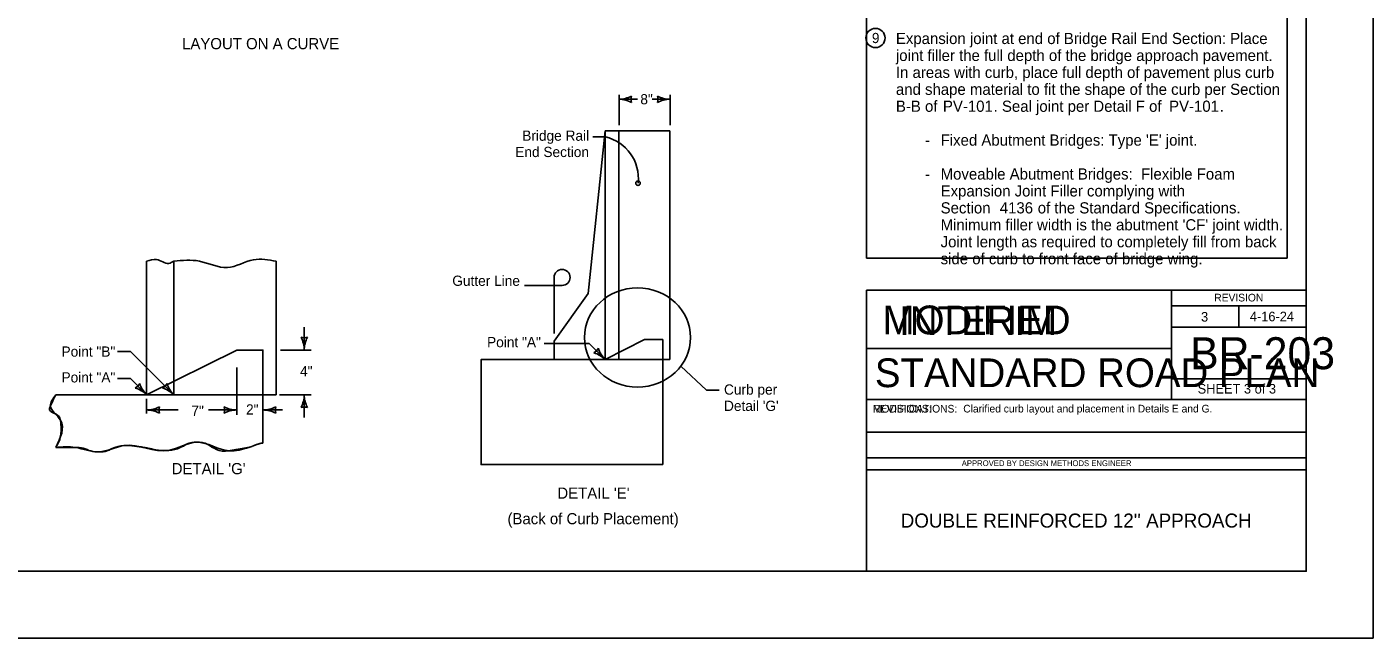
# Model space of a CAD drawing. Extents: x -2135039 to -2124495, y -2139046 to -2132546.
# Drawn here: x -2126601 to -2124495, y -2135130 to -2134174 of the extents above; entities that cross this region are included whole.
import ezdxf

# ---------------------------------------------------------------- set-up
doc = ezdxf.new("R2010")
doc.units = 0
for name, color, linetype in [('Barrier', 7, 'Continuous'), ('BridgeSuperStructureExisting', 7, 'Continuous'), ('Dimension', 7, 'Continuous'), ('dsnAlignmentCurveData', 7, 'Continuous'), ('dsnAlignmentStation', 7, 'Continuous'), ('dsnAlignmentTic', 7, 'Continuous'), ('dsnCellElements', 7, 'Continuous'), ('DsnShtPlotIdentification', 7, 'Continuous'), ('dsnStdLabel', 7, 'Continuous'), ('dsnStdLineWork', 7, 'Continuous'), ('PhoEdgeShoulderPaved', 7, 'Continuous'), ('TC_Barrier', 7, 'Continuous')]:
    doc.layers.add(name, color=color, linetype=linetype)

msp = doc.modelspace()

# ---------------------------------------------------------------- linework, layer by layer
at = {"layer": 'BridgeSuperStructureExisting'}
for p, q in [((-2125674.7, -2134328), (-2125674.7, -2134280.7)), ((-2125594.7, -2134328), (-2125594.7, -2134280.7)), ((-2125675, -2134287.4), (-2125645.9, -2134287.4)), ((-2125623, -2134287.4), (-2125594.7, -2134287.4)), ((-2125723, -2134591.1), (-2125696.3, -2134337.1)), ((-2125696, -2134346.3), (-2125715.5, -2134346.3)), ((-2125696.3, -2134337.1), (-2125595, -2134337.1)), ((-2125696.3, -2134337.1), (-2125696.3, -2134694.7)), ((-2125675, -2134337.1), (-2125675, -2134683.7)), ((-2125595, -2134337.1), (-2125595, -2134694.7)), ((-2126413.9, -2134540.8), (-2126413.9, -2134749.8)), ((-2126371.2, -2134540.8), (-2126371.2, -2134728.7)), ((-2126211.2, -2134540.8), (-2126211.2, -2134749.7)), ((-2125822.7, -2134578.7), (-2125783.8, -2134578.7)), ((-2125776.3, -2134654.1), (-2125776.3, -2134586.2)), ((-2125776.3, -2134665.8), (-2125723, -2134591.1)), ((-2125595, -2134631.5), (-2125595, -2134663.1)), ((-2126167.2, -2134644.1), (-2126167.2, -2134679.8)), ((-2126459.3, -2134682.2), (-2126438.8, -2134682.2)), ((-2126438.8, -2134682.2), (-2126371.2, -2134749.8)), ((-2126231.8, -2134679.8), (-2126272.5, -2134679.8)), ((-2126231.8, -2134825.3), (-2126231.8, -2134679.8)), ((-2126204.4, -2134679.8), (-2126156.5, -2134679.8)), ((-2125721.6, -2134669.4), (-2125791.9, -2134669.4)), ((-2125776.3, -2134694.7), (-2125776.3, -2134665.8)), ((-2125721.6, -2134669.4), (-2125696.3, -2134694.7)), ((-2125606, -2134663.1), (-2125635, -2134663.1)), ((-2125635, -2134663.1), (-2125606, -2134663.1)), ((-2125606, -2134858.9), (-2125606, -2134663.1)), ((-2125606, -2134663.1), (-2125606, -2134858.9)), ((-2125696.3, -2134694.7), (-2125606, -2134694.7)), ((-2125675, -2134683.7), (-2125675, -2134694.7)), ((-2125606, -2134694.7), (-2125595, -2134694.7)), ((-2126439.1, -2134724.6), (-2126459.3, -2134724.6)), ((-2126439.1, -2134724.6), (-2126413.9, -2134749.8)), ((-2126272.7, -2134707.2), (-2126272.7, -2134781.1)), ((-2125578, -2134705.1), (-2125538, -2134742.8)), ((-2126371.2, -2134728.7), (-2126371.2, -2134749.8)), ((-2125538, -2134742.8), (-2125518.2, -2134742.8)), ((-2126555.9, -2134749.8), (-2126413.9, -2134749.8)), ((-2126413.8, -2134749.8), (-2126415, -2134749.8)), ((-2126231.8, -2134749.8), (-2126413.9, -2134749.8)), ((-2126413.9, -2134756.1), (-2126413.9, -2134779.1)), ((-2126231.8, -2134749.8), (-2126211.2, -2134749.8)), ((-2126206, -2134749.7), (-2126156.5, -2134749.7)), ((-2126167.2, -2134749.7), (-2126167.2, -2134785.5)), ((-2126413.8, -2134773.6), (-2126364.4, -2134773.6)), ((-2126316.8, -2134773.6), (-2126272.7, -2134773.6)), ((-2126231.8, -2134773.6), (-2126201.3, -2134773.6))]:
    msp.add_line(p, q, dxfattribs=at)
for points in [[(-2126231.8, -2134825.3), (-2126231.8, -2134679.8), (-2126272.5, -2134679.8), (-2126413.9, -2134749.8), (-2126555.9, -2134749.8)], [(-2126413.9, -2134749.8), (-2126272.5, -2134679.8)], [(-2125696.3, -2134694.7), (-2125635, -2134663.1)], [(-2125696.3, -2134694.7), (-2125635, -2134663.1)], [(-2125606, -2134858.9), (-2125890.4, -2134858.9), (-2125890.4, -2134694.7), (-2125744.3, -2134694.7), (-2125696.3, -2134694.7)], [(-2125606, -2134858.9), (-2125890.4, -2134858.9), (-2125890.4, -2134694.7), (-2125744.3, -2134694.7), (-2125696.3, -2134694.7)]]:
    msp.add_lwpolyline(points, dxfattribs=at)
msp.add_circle((-2125273.5, -2134191.6), 15, dxfattribs=at)
msp.add_arc((-2125711.1, -2134411.2), 66.7, 353.5756, 76.8823, dxfattribs=at)
msp.add_ellipse((-2125645.7, -2134660.1), major_axis=(83, 0), ratio=0.93542, dxfattribs=at)
for points in [[(-2126413.9, -2134540.8), (-2126398.2, -2134538.3), (-2126379.1, -2134544.2), (-2126371.2, -2134540.8)], [(-2126371.2, -2134540.8), (-2126331.1, -2134540.8), (-2126287.4, -2134550.8), (-2126246.6, -2134538.6), (-2126211.2, -2134540.8)], [(-2126555.9, -2134749.8), (-2126564.2, -2134767.4), (-2126548.5, -2134789.6), (-2126555.7, -2134832.2)], [(-2126555.7, -2134832.2), (-2126525.2, -2134832.2), (-2126489, -2134839.2), (-2126449.3, -2134829.3), (-2126379.4, -2134836.9), (-2126335.6, -2134824.1), (-2126284.3, -2134837.5), (-2126253.8, -2134832.2)]]:
    msp.add_spline(points, degree=3, dxfattribs=at)
for points, degree in [([(-2126555.9, -2134749.8), (-2126558.7, -2134755.7), (-2126561.5, -2134761.5), (-2126564.2, -2134767.4), (-2126568.1, -2134775.6), (-2126549.5, -2134781.8), (-2126548.5, -2134789.6), (-2126547, -2134801.9), (-2126548.1, -2134819.7), (-2126555.7, -2134832.2)], 3), ([(-2126555.7, -2134832.2), (-2126545.5, -2134832.2), (-2126535.4, -2134832.2), (-2126525.2, -2134832.2), (-2126512.9, -2134832.2), (-2126501, -2134838.8), (-2126489, -2134839.2), (-2126475.7, -2134839.7), (-2126462.6, -2134830.1), (-2126449.3, -2134829.3)], 3), ([(-2126449.3, -2134829.3), (-2126442.2, -2134828.9), (-2126435, -2134829.6), (-2126427.7, -2134830.7)], 2), ([(-2126427.7, -2134830.7), (-2126411.5, -2134833.1), (-2126395, -2134837.6), (-2126379.4, -2134836.9)], 2), ([(-2126379.4, -2134836.9), (-2126364.6, -2134836.2), (-2126350.3, -2134824.4), (-2126335.6, -2134824.1), (-2126318.5, -2134823.6), (-2126301.7, -2134840.5), (-2126284.3, -2134837.5)], 3), ([(-2126253.8, -2134832.2), (-2126252.9, -2134832), (-2126251.9, -2134831.7), (-2126251, -2134831.3), (-2126250.1, -2134831), (-2126249.2, -2134830.7), (-2126248.3, -2134830.3), (-2126246.4, -2134829.6), (-2126244.6, -2134828.9), (-2126242.8, -2134828.2), (-2126241, -2134827.5), (-2126239.1, -2134826.9), (-2126237.3, -2134826.3), (-2126236.4, -2134826), (-2126235.5, -2134825.8), (-2126234.5, -2134825.6), (-2126234.1, -2134825.6), (-2126233.6, -2134825.5), (-2126233.2, -2134825.4), (-2126232.7, -2134825.4), (-2126232.3, -2134825.3), (-2126231.8, -2134825.3)], 3), ([(-2126253.8, -2134832.2), (-2126252.9, -2134832), (-2126251.9, -2134831.7), (-2126251, -2134831.3), (-2126250.1, -2134831), (-2126249.2, -2134830.7), (-2126248.3, -2134830.3), (-2126246.4, -2134829.6), (-2126244.6, -2134828.9), (-2126242.8, -2134828.2), (-2126241, -2134827.5), (-2126239.1, -2134826.9), (-2126237.3, -2134826.3), (-2126236.4, -2134826), (-2126235.5, -2134825.8), (-2126234.5, -2134825.6), (-2126234.1, -2134825.6), (-2126233.6, -2134825.5), (-2126233.2, -2134825.4), (-2126232.7, -2134825.4), (-2126232.3, -2134825.3), (-2126231.8, -2134825.3)], 3), ([(-2126284.3, -2134837.5), (-2126278.3, -2134836.4), (-2126272.3, -2134835.4), (-2126266.3, -2134834.4)], 2), ([(-2126266.3, -2134834.4), (-2126262.2, -2134833.7), (-2126258, -2134832.9), (-2126253.8, -2134832.2)], 2)]:
    msp.add_open_spline(points, degree=degree, dxfattribs=at)
at = {"layer": 'Dimension'}
for p, q in [((-2124810.4, -2134585.9), (-2124810.4, -2134677.3)), ((-2124810.4, -2134610.9), (-2124599.4, -2134610.9)), ((-2124704.9, -2134610.9), (-2124704.9, -2134644.1)), ((-2124810.4, -2134644.1), (-2124599.4, -2134644.1)), ((-2125287.5, -2134677.3), (-2124810.4, -2134677.3)), ((-2124810.4, -2134677.3), (-2124810.4, -2134757.3)), ((-2124599.4, -2134725.1), (-2124810.4, -2134725.1)), ((-2125287.5, -2134757.3), (-2124599.4, -2134757.3)), ((-2125287.5, -2134808.3), (-2124599.4, -2134808.3)), ((-2125287.5, -2134848.3), (-2124599.4, -2134848.3)), ((-2125287.5, -2134867.3), (-2124599.4, -2134867.3))]:
    msp.add_line(p, q, dxfattribs=at)
msp.add_lwpolyline([(-2125287.5, -2134585.9), (-2124599.4, -2134585.9), (-2124599.4, -2135026), (-2125287.5, -2135026)], close=True, dxfattribs=at)
msp.add_lwpolyline([(-2125287.5, -2134585.9), (-2124599.4, -2134585.9), (-2124599.4, -2135026), (-2125287.5, -2135026)], close=True, dxfattribs=at)
at = {"layer": 'dsnAlignmentStation'}
msp.add_lwpolyline([(-2127734.4, -2133016), (-2124599.4, -2133016), (-2124599.4, -2135026), (-2127734.4, -2135026)], close=True, dxfattribs=at)
at = {"layer": 'dsnCellElements'}
for centre, radius, start, end in [((-2125675, -2134244.9), 42.5, 270, 298.0725), ((-2125639.3, -2134287.4), 16.4, 162.2666, 197.7334), ((-2125630.3, -2134287.4), 16.4, 342.2666, 17.7333), ((-2125594.7, -2134244.9), 42.5, 241.9275, 270), ((-2125675, -2134329.9), 42.5, 61.9275, 90), ((-2125594.7, -2134329.9), 42.5, 90, 118.0725), ((-2126167.2, -2134644.2), 16.4, 252.2666, 287.7333), ((-2126209.7, -2134679.8), 42.5, 360, 28.0725), ((-2126124.7, -2134679.8), 42.5, 151.9275, 180), ((-2125721.5, -2134669.5), 16.4, 297.2666, 332.7333), ((-2125666.2, -2134664.7), 42.5, 196.9275, 225), ((-2125726.3, -2134724.8), 42.5, 45, 73.0725), ((-2126439.1, -2134724.6), 16.4, 297.2666, 332.7333), ((-2126443.9, -2134779.9), 42.5, 45, 73.0725), ((-2126383.8, -2134719.8), 42.5, 196.9275, 225), ((-2126396.4, -2134724.6), 16.4, 297.2666, 332.7333), ((-2126401.3, -2134779.9), 42.5, 45, 73.0725), ((-2126341.2, -2134719.8), 42.5, 196.9275, 225), ((-2126209.7, -2134749.7), 42.5, 331.9275, 360), ((-2126124.7, -2134749.7), 42.5, 180, 208.0725), ((-2126413.8, -2134731.1), 42.5, 270, 298.0725), ((-2126413.8, -2134816.1), 42.5, 61.9275, 90), ((-2126378.1, -2134773.6), 16.4, 162.2666, 197.7334), ((-2126308.3, -2134773.6), 16.4, 342.2666, 17.7333), ((-2126272.7, -2134731.1), 42.5, 241.9275, 270), ((-2126272.7, -2134816.1), 42.5, 90, 118.0725), ((-2126231.8, -2134731.1), 42.5, 270, 298.0725), ((-2126231.8, -2134816.1), 42.5, 61.9275, 90), ((-2126196.1, -2134773.6), 16.4, 162.2666, 197.7334), ((-2126167.2, -2134785.4), 16.4, 72.2666, 107.7334)]:
    msp.add_arc(centre, radius, start, end, dxfattribs=at)
at = {"layer": 'dsnStdLineWork'}
msp.add_lwpolyline([(-2127838.9, -2135130.5), (-2124494.9, -2135130.5), (-2124494.9, -2132546.5), (-2127838.9, -2132546.5)], close=True, dxfattribs=at)
at = {"layer": 'PhoEdgeShoulderPaved'}
for p, q in [((-2125287.5, -2133066), (-2125287.5, -2134535.9)), ((-2124629.4, -2133066), (-2124629.4, -2134535.9)), ((-2124629.4, -2134535.9), (-2125287.5, -2134535.9))]:
    msp.add_line(p, q, dxfattribs=at)
at = {"layer": 'TC_Barrier'}
for p, q in [((-2125776.3, -2134586.2), (-2125776.3, -2134566.2)), ((-2125763.8, -2134578.7), (-2125783.8, -2134578.7))]:
    msp.add_line(p, q, dxfattribs=at)
msp.add_circle((-2125644.9, -2134418.7), 3.54, dxfattribs=at)
msp.add_arc((-2125763.8, -2134566.2), 12.5, 270, 180, dxfattribs=at)

# ---------------------------------------------------------------- texts
at = {"layer": 'Barrier'}
for s, height, p in [('9', 16, (-2125279.1, -2134199.6)), ('Expansion joint at end of Bridge Rail End Section: Place', 17.5, (-2125241.5, -2134201.1)), ('joint filler the full depth of the bridge approach pavement.', 17.5, (-2125241.5, -2134227.6)), ('In areas with curb, place full depth of pavement plus curb', 17.5, (-2125241.5, -2134254.1)), ('and shape material to fit the shape of the curb per Section', 17.5, (-2125241.5, -2134280.6)), ('B-B of ', 17.5, (-2125241.5, -2134307.1)), ('PV-101', 17.5, (-2125167.9, -2134307.1)), ('PV-101', 17.5, (-2125167.9, -2134307.1)), ('. Seal joint per Detail F of ', 17.5, (-2125088.6, -2134307.1)), ('PV-101', 17.5, (-2124814.1, -2134307.1)), ('PV-101', 17.5, (-2124814.1, -2134307.1)), ('.', 17.5, (-2124734.8, -2134307.1)), ("Fixed Abutment Bridges: Type 'E' joint.", 17.5, (-2125171.5, -2134360.1)), ('       -', 17.5, (-2125241.5, -2134360.1)), ('       -', 17.5, (-2125241.5, -2134413.1)), ('Moveable Abutment Bridges:  Flexible Foam', 17.5, (-2125171.5, -2134413.1)), ('Expansion Joint Filler complying with ', 17.5, (-2125171.5, -2134439.6)), ('Section ', 17.5, (-2125171.5, -2134466.1)), ('4136', 17.5, (-2125079, -2134466.1)), ('4136', 17.5, (-2125079, -2134466.1)), (' of the Standard Specifications.', 17.5, (-2125026.1, -2134466.1)), ("Minimum filler width is the abutment 'CF' joint width.", 17.5, (-2125171.5, -2134492.6)), ('Joint length as required to completely fill from back ', 17.5, (-2125171.5, -2134519.1)), ('side of curb to front face of bridge wing.', 17.5, (-2125171.5, -2134545.6))]:
    msp.add_text(s, height=height, dxfattribs=at).set_placement(p)
at = {"layer": 'BridgeSuperStructureExisting'}
for s, height, p in [('LAYOUT ON A CURVE', 17.5, (-2126358.3, -2134209.2)), ('8"', 16, (-2125641.3, -2134295.4)), ('Bridge Rail ', 16, (-2125826.1, -2134352.4)), ('End Section', 16, (-2125837, -2134377.9)), ('Gutter Line', 16, (-2125935.5, -2134579.4)), ('Point "A"', 16, (-2125881.1, -2134675.4)), ('Point "B"', 16, (-2126546.9, -2134690.2)), ('Point "A"', 16, (-2126546.9, -2134730.5)), ('4"', 16, (-2126173.7, -2134720.9)), ('Curb per', 16, (-2125510.4, -2134749.6)), ('7"', 16, (-2126343.7, -2134782.8)), ('2"', 16, (-2126258.2, -2134780.7)), ("Detail 'G'", 16, (-2125510.4, -2134775.1)), ("DETAIL 'G'", 17.5, (-2126374.5, -2134874.1)), ("DETAIL 'E'", 17.5, (-2125771.1, -2134912.4))]:
    msp.add_text(s, height=height, dxfattribs=at).set_placement(p)
at = {"layer": 'Dimension'}
for s, height, p in [('REVISION', 12, (-2124743.4, -2134603.8)), ('3', 15, (-2124764.1, -2134635.3)), ('4-16-24', 15, (-2124687.8, -2134634.8)), ('BR-203', 50, (-2124781.2, -2134709.8)), ('STANDARD ROAD PLAN', 45.001, (-2125274.4, -2134737.9)), ('SHEET 3 of 3', 15, (-2124769.4, -2134747.9)), ('Clarified curb layout and placement in Details E and G.', 12, (-2125136.1, -2134777.5)), ('APPROVED BY DESIGN METHODS ENGINEER', 9.003, (-2125138.5, -2134861.4)), ("DOUBLE REINFORCED 12'' APPROACH", 22, (-2125234, -2134957.6))]:
    msp.add_text(s, height=height, dxfattribs=at).set_placement(p)
at = {"layer": 'dsnAlignmentCurveData'}
msp.add_text('REVISIONS:', height=12, dxfattribs=at).set_placement((-2125277.5, -2134777.6))
at = {"layer": 'dsnAlignmentTic'}
for s, height, p in [('MODIFIED', 45, (-2125262.4, -2134655.2)), ('MODIFICATIONS:', 12, (-2125277.5, -2134777.6))]:
    msp.add_text(s, height=height, dxfattribs=at).set_placement(p)
at = {"layer": 'DsnShtPlotIdentification'}
msp.add_text('INTERIM', height=45, dxfattribs=at).set_placement((-2125236.5, -2134656.3))
at = {"layer": 'dsnStdLabel'}
msp.add_text('(Back of Curb Placement)', height=17.5, dxfattribs=at).set_placement((-2125849.2, -2134952.4))

doc.saveas('drawing.dxf')
